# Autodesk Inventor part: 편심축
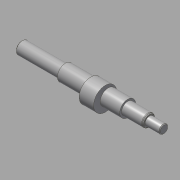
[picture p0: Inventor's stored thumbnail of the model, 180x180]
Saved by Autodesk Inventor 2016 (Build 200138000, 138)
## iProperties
Created: 2016-05
Part Number: 편심축
Document SubType Name: Modeling
Designer: mduedu
Density: 7.86 g/cm^3
Material: 강철, 연강
Appearance: 강철
Author: mduedu
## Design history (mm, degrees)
sketch "스케치1"
  geometry: L1 (-38, 11)-(-38, 8.5); L2 (48, 11)-(48, 8.5); L3 (-98, 0)-(98, 0); L4 (-38, 11)-(48, 11); L5 (48, 11)-(48, 8.5); L6 (-38, 11)-(-38, 8.5); L7 (-38, 8.5)-(-98, 8.5); L8 (-98, 8.5)-(-98, 0); L9 (48, 8.5)-(78, 8.5); L10 (98, 6)-(98, 0); L11 (78, 8.5)-(78, 6); L12 (78, 6)-(98, 6); 1 further point
  constraints: 24 end point, 9 perpendicular, 2 midpoint, 1 collinear, 1 horizontal
  dimensions: "d0" = 22 diameter of L4 L3; "d1" = 17 diameter of L7 L3; "d2" = 60 distance between parallel lines of L8 L1; "d3" = 50 distance between parallel lines of L10 L2; "d4" = 12 diameter of L12 L3; "d5" = 20 distance between parallel lines of L10 L11; "d29" = 86 distance of L1.start L2.start
revolve "회전1" stored, may be unused: angle "d6" = 90 deg
node "작업 평면7"
node "작업 평면9"
sketch "스케치2"
  geometry: C1 r 11 at (0, 0); C2 r 16 at (0, -4); C3 r 11 at (0, 0); 2 further points
  constraints: 3 centre point, 2 coincident, 1 concentric, 1 vertical alignment
  dimensions: "d9" = 4 distance of point (0, 0) C2.centre; "d10" = 32 diameter of C2
extrude "돌출1" join sketch "스케치2" stored distance "d11" = 20; taper "d12" = 0 deg
chamfer "모따기2" distance "d32" = 1; stored, may be unused: second distance "d33" = 2, angle "d34" = 45 deg
node "작업 평면4"
sketch "스케치4"
  geometry: L1 (-5, 2)-(5, 2); L2 (5, -2)-(-5, -2); L3 (-10, -5)-(-10, 5) reference; A1 r 2 centre (5, 0) between (5, -2) and (5, 2); A2 r 2 centre (-5, 0) between (-5, 2) and (-5, -2); 2 further points
  constraints: 4 end point, 4 point on circle, 4 tangent, 2 centre point, 2 horizontal alignment, 1 midpoint, 1 parallel
  dimensions: "d20" = 4 distance between parallel lines of L2 L1; "d21" = 14 dimension on A1 A2; "d35" = 3 distance edge to line of A2 L3
extrude "돌출3" cut sketch "스케치4" distance "d23" = 2.5; taper "d24" = 0 deg
node "작업 평면5"
sketch "스케치5"
  geometry: L1 (30, 2.5)-(12.5, 2.5); L2 (12.5, -2.5)-(30, -2.5); L3 (30, 7.5)-(30, -7.5) reference; A1 r 2.5 centre (12.5, 0) between (12.5, 2.5) and (12.5, -2.5); 2 further points
  constraints: 4 end point, 2 point on circle, 2 point on line, 2 tangent, 1 centre point, 1 horizontal, 1 horizontal alignment, 1 midpoint
  dimensions: "d25" = 5 distance between parallel lines of L2 L1; "d36" = 20 dimension on A1 L3
extrude "돌출4" cut sketch "스케치5" distance "d27" = 3; taper "d28" = 0 deg
chamfer "모따기3" distance "d37" = 1.82; stored, may be unused: second distance "d38" = 2, angle "d39" = 30 deg
fillet "모깎기1" dims "d40" = 2, "d41" = 0.5
node "솔리드1"
other parameters: "d31" = -37
